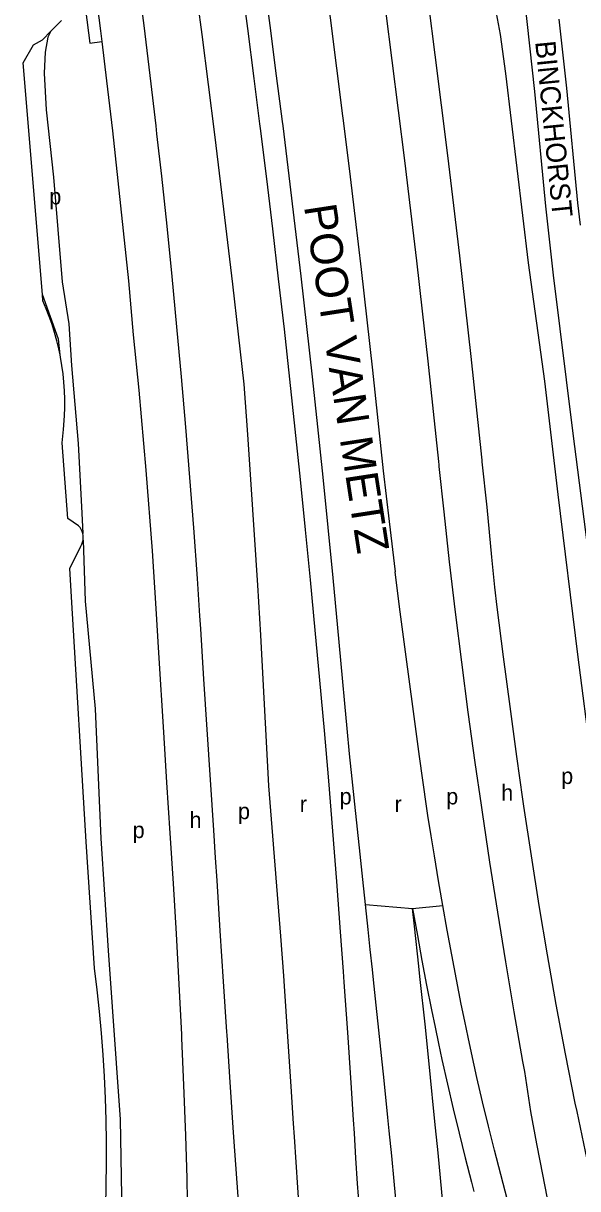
# Model space of a CAD drawing. Extents: x 157646 to 159241, y 379213 to 381217.
# Drawn here: x 157924.4 to 158061.7, y 379962.3 to 380250.8 of the extents above; entities that cross this region are included whole.
import ezdxf

# ---------------------------------------------------------------- set-up
doc = ezdxf.new("R2010")
doc.units = 0
for name, color, linetype in [('BLT_Basislijn', 7, 'Continuous'), ('BLT_Centroide', 7, 'Continuous'), ('BLT_Gemeentegrens', 7, 'Continuous'), ('BLT_Straatnaam', 7, 'Continuous'), ('BLT_Straatnaam_hoofdweg', 7, 'Continuous'), ('BLT_Vlakafsluiter', 7, 'Continuous')]:
    doc.layers.add(name, color=color, linetype=linetype)

msp = doc.modelspace()

# ---------------------------------------------------------------- linework, layer by layer
at = {"layer": 'BLT_Basislijn'}
for points in [[(157939.43, 380280.31), (157940.34, 380273.64), (157941.97, 380261.3), (157943.53, 380248.95), (157943.85, 380246.32)], [(158043.52, 380272.26), (158043.86, 380272.1), (158045.23, 380270.58), (158046.3, 380268.97), (158047.18, 380265.9), (158048.5, 380256.56), (158050.97, 380233.98), (158053.72, 380205.54), (158055.59, 380188.47), (158060.48, 380149.25), (158065.1, 380113.27), (158072.13, 380063.15), (158075.51, 380040.61), (158083.37, 379989.94), (158090.54, 379947.99)], [(158026.51, 380266.17), (158028.27, 380266.84), (158030.04, 380266.89), (158032.44, 380266.09), (158034.37, 380265.02), (158036.46, 380263.3), (158038.06, 380261.59), (158039.72, 380259.45), (158040.69, 380257.15), (158041.27, 380254.63), (158042.46, 380248.09), (158043.78, 380238.44), (158049.4, 380191.53), (158053.5, 380162.19), (158056.77, 380134.16), (158061.6, 380094.53), (158065.06, 380068.3), (158072.73, 380012.87), (158077.32, 379983.19), (158084.04, 379946.64)], [(158012.95, 380262.61), (158014.09, 380254.03), (158015.7, 380241.63), (158017.27, 380229.24)], [(157999.24, 380260.63), (158000.36, 380252.21), (158001.97, 380239.76), (158003.47, 380227.91)], [(157983.01, 380225.94), (157981.59, 380237.15), (157979.98, 380249.54), (157978.9, 380257.67)], [(157988.59, 380226.48), (157987.14, 380237.86), (157985.53, 380250.27), (157984.44, 380258.48)], [(157939.8, 380254.28), (157940.91, 380245.93), (157943.85, 380246.32)], [(157953.78, 380254.03), (157954.25, 380250.28), (157955.76, 380237.87), (157957.21, 380225.45), (157957.43, 380223.47)], [(157967.52, 380256.02), (157968.58, 380248.04), (157970.18, 380235.69), (157971.75, 380223.33), (157973.27, 380210.97), (157974.76, 380198.6), (157976.21, 380186.23), (157977.62, 380173.86), (157978.99, 380161.48), (157979.9, 380149.05), (157980.76, 380136.62), (157981.59, 380124.18), (157982.37, 380111.75), (157983.12, 380099.32), (157983.83, 380086.88), (157984.5, 380074.45), (157985.13, 380062.01), (157986.15, 380049.61), (157987.14, 380037.2), (157988.08, 380024.79), (157988.8, 380014.99), (157988.99, 380012.38), (157989.86, 379999.97), (157990.68, 379987.55), (157991.27, 379978.4), (157991.48, 379975.11), (157991.87, 379968.85), (157992.28, 379962.57), (157992.72, 379956.27)], [(158061.1, 379983.47), (158058.68, 379995.67), (158056.39, 380007.9), (158054.21, 380020.14), (158052.15, 380032.41), (158050.23, 380044.69), (158048.39, 380056.99), (158048.14, 380058.72), (158046.62, 380069.3), (158044.93, 380081.63), (158043.31, 380093.96), (158041.78, 380106.3), (158041.18, 380111.24), (158040.43, 380118.66), (158039.23, 380131.04), (158038.05, 380142.24), (158038.03, 380142.42), (158038.01, 380142.63), (158037.93, 380143.42), (158036.62, 380155.88), (158035.28, 380168.34), (158033.9, 380180.8), (158032.48, 380193.25), (158031.02, 380205.7), (158029.52, 380218.14), (158027.98, 380230.58), (158026.41, 380243.01), (158024.79, 380255.44)], [(158057.05, 380251.88), (158058.92, 380234.8), (158061.68, 380206.36), (158062.28, 380200.88)], [(157931.26, 380248.87), (157930.46, 380247.36), (157929.82, 380243.72), (157929.55, 380238.48), (157930.03, 380229.38), (157931.89, 380212.75), (157934.05, 380186.8), (157935.64, 380176.4), (157936.32, 380166.13), (157937.96, 380146.78), (157938.94, 380129.57), (157939.13, 380124.53)], [(157943.85, 380246.32), (157945.04, 380236.59), (157946.48, 380224.23), (157947.85, 380211.86), (157949.17, 380199.48), (157950.43, 380187.09), (157951.62, 380173.67), (157952.99, 380160.03), (157954.75, 380140.2), (157956.28, 380120.24), (157957.25, 380105.96), (157957.91, 380094.92), (157959.09, 380075.28), (157959.9, 380062.81), (157960.71, 380050.34), (157961.51, 380037.86), (157962.26, 380025.38), (157962.94, 380012.9), (157963.55, 380000.42), (157963.59, 379999.54), (157964.09, 379987.92), (157964.56, 379975.43)], [(158003.47, 380227.91), (158003.55, 380227.31), (158005.09, 380214.85), (158006.59, 380202.38), (158008.05, 380189.91), (158009.47, 380177.43), (158010.85, 380164.96), (158012.2, 380152.47), (158013.5, 380139.98), (158014.97, 380127.51), (158016.49, 380115.05)], [(158017.27, 380229.24), (158017.27, 380229.23), (158018.8, 380216.83), (158020.29, 380204.42), (158021.75, 380192.01), (158023.17, 380179.59), (158024.54, 380167.17), (158025.88, 380154.74), (158027.18, 380142.31), (158027.27, 380141.52), (158027.29, 380141.32), (158027.31, 380141.13), (158028.5, 380129.88), (158029.89, 380117.45), (158031.35, 380105.04), (158032.9, 380092.63), (158034.52, 380080.23), (158036.22, 380067.84), (158037.75, 380057.2), (158038, 380055.47), (158039.85, 380043.1), (158041.79, 380030.75), (158043.79, 380018.41), (158045.88, 380006.08), (158048.04, 379993.77), (158048.49, 379991.31), (158049.99, 379981.41), (158051.5, 379973.34), (158052.31, 379969.13), (158054.7, 379956.85)], [(158007.63, 379957.32), (158007.2, 379963.57), (158006.79, 379969.81), (158006.4, 379976.05), (158006.19, 379979.33), (158005.6, 379988.52), (158004.77, 380000.98), (158003.9, 380013.45), (158003.71, 380016.06), (158002.99, 380025.9), (158002.04, 380038.36), (158001.06, 380050.81), (158000.03, 380063.26), (157998.97, 380075.71), (157997.86, 380088.15), (157996.72, 380100.59), (157995.54, 380113.02), (157994.32, 380125.45), (157993.06, 380137.88), (157991.76, 380150.3), (157990.42, 380162.72), (157989.05, 380175.14), (157987.63, 380187.55), (157986.18, 380199.96), (157984.69, 380212.36), (157983.16, 380224.76), (157983.01, 380225.94)], [(158009.14, 380032.63), (158008.46, 380038.86), (158007.8, 380045.08), (158007.14, 380051.3), (158006.48, 380057.52), (158005.84, 380063.75), (158005.22, 380069.97), (158004.61, 380076.2), (158004.01, 380082.42), (158003.44, 380088.65), (158002.3, 380101.11), (158001.11, 380113.56), (157999.89, 380126.01), (157998.63, 380138.45), (157997.33, 380150.9), (157995.99, 380163.33), (157994.61, 380175.77), (157993.2, 380188.19), (157991.74, 380200.62), (157990.25, 380213.04), (157988.72, 380225.45), (157988.59, 380226.48)], [(157957.43, 380223.47), (157958.59, 380213.02), (157959.91, 380200.59), (157961.17, 380188.15), (157962.37, 380175.71), (157963.51, 380163.26), (157964.58, 380150.8), (157965.59, 380138.34), (157966.54, 380125.88), (157967.43, 380113.4), (157968.05, 380104.09), (157968.25, 380100.93), (157969.06, 380088.46), (157969.87, 380075.98), (157970.68, 380063.51), (157971.49, 380051.03), (157971.93, 380044.23)], [(157933.51, 380168.73), (157933.14, 380172.65), (157929.13, 380183.68)], [(157939.19, 380122.86), (157939.76, 380107.77), (157942.22, 380081.05), (157943.61, 380048.96), (157945.41, 380021.26), (157948.42, 379979.43), (157948.94, 379946.33), (157948.13, 379919.94), (157948.45, 379894.86), (157946.98, 379860.6), (157943.7, 379835.03), (157942.15, 379812.53), (157941.26, 379794.25)], [(158028.29, 380032.4), (158027.47, 380037.13), (158027.23, 380038.53), (158026.21, 380044.66), (158025.4, 380049.68), (158024.59, 380054.71), (158024.27, 380056.96), (158022.52, 380069.3), (158020.83, 380081.64), (158019.18, 380093.98), (158017.59, 380106.34), (158016.49, 380115.05)], [(157971.93, 380044.23), (157972.29, 380038.56), (157973.1, 380026.09), (157973.91, 380013.61), (157974.72, 380001.14), (157974.78, 380000.26), (157975.53, 379988.67), (157976.34, 379976.19), (157977.26, 379963.73), (157978.19, 379951.26), (157979.11, 379938.79), (157979.92, 379926.32), (157980.73, 379913.85)], [(158016.85, 379957.97), (158016.24, 379964.17), (158015.63, 379970.38), (158015.02, 379976.6), (158014.7, 379979.87), (158013.78, 379989.05), (158013.14, 379995.28), (158012.48, 380001.51), (158011.82, 380007.74), (158011.16, 380013.96), (158010.87, 380016.58), (158010.34, 380021.5), (158009.81, 380026.41), (158009.14, 380032.63)], [(158020.8, 380031.65), (158021.99, 380024.95), (158023.11, 380018.8), (158024.28, 380012.66), (158025.5, 380006.52), (158026.37, 380002.24), (158027.21, 379998.25), (158028.07, 379994.27), (158029.43, 379988.17), (158030.85, 379982.07), (158032.31, 379975.99), (158033.83, 379969.92), (158035.4, 379963.86), (158035.99, 379961.61)], [(158028.33, 379958.79), (158027.71, 379964.94), (158027.11, 379971.12), (158026.5, 379977.32), (158026.18, 379980.59), (158025.25, 379989.8), (158023.96, 380002.29), (158022.63, 380014.78), (158022.34, 380017.4), (158021.28, 380027.27), (158020.8, 380031.65)], [(158044.25, 379959.79), (158043.24, 379963.54), (158042.65, 379965.77), (158041.1, 379971.77), (158039.6, 379977.78), (158038.15, 379983.8), (158036.75, 379989.83), (158035.4, 379995.88), (158034.55, 379999.82), (158033.72, 380003.76), (158032.85, 380008), (158031.65, 380014.08), (158030.49, 380020.18), (158029.37, 380026.28), (158028.29, 380032.4)], [(158072.5, 379932.76), (158071.31, 379937.57), (158070.15, 379942.39), (158069.57, 379944.86), (158067.13, 379955.38), (158066.77, 379956.99), (158064.09, 379969.16), (158064.01, 379969.53), (158061.53, 379981.35), (158061.1, 379983.47)], [(157964.56, 379975.43), (157964.9, 379964.81), (157964.94, 379963.61), (157965.27, 379951.11), (157965.38, 379945.95), (157965.53, 379938.61), (157965.72, 379926.12), (157965.82, 379915.79), (157965.83, 379913.62), (157965.87, 379905.85)]]:
    msp.add_lwpolyline(points, dxfattribs=at)
at = {"layer": 'BLT_Gemeentegrens'}
for points in [[(157931.26, 380248.87), (157933.83, 380251.5)], [(157929.13, 380183.68), (157924.41, 380241.04), (157926.94, 380245.51), (157929.2, 380246.77), (157931.26, 380248.87)], [(157933.51, 380168.73), (157933.21, 380170.21), (157932.72, 380172.24), (157932.16, 380174.25), (157931.54, 380176.25), (157930.85, 380178.22), (157930.09, 380180.16), (157929.27, 380182.09), (157929.13, 380183.68)], [(157939.13, 380124.53), (157938.97, 380125.04), (157938.74, 380125.52), (157938.45, 380125.98), (157938.1, 380126.39), (157935.46, 380128.22), (157934.04, 380146.94), (157934.34, 380150.27), (157934.58, 380153.6), (157934.66, 380155.69), (157934.66, 380157.78), (157934.6, 380159.87), (157934.46, 380161.95), (157934.25, 380164.03), (157933.97, 380166.1), (157933.63, 380168.16), (157933.51, 380168.73)], [(157939.19, 380122.86), (157939.2, 380122.91), (157939.25, 380123.45), (157939.23, 380123.99), (157939.13, 380124.52), (157939.13, 380124.53)], [(157944.83, 379957.74), (157944.96, 379963.12), (157945.02, 379968.51), (157945, 379973.89), (157944.9, 379979.28), (157944.73, 379984.66), (157944.48, 379990.04), (157944.15, 379995.41), (157943.74, 380000.79), (157943.26, 380006.15), (157942.7, 380011.5), (157942.07, 380016.85), (157940.01, 380048.18), (157936.41, 380107.39), (157935.89, 380115.87), (157938.64, 380121.4), (157938.9, 380121.87), (157939.08, 380122.38), (157939.19, 380122.86)]]:
    msp.add_lwpolyline(points, dxfattribs=at)
at = {"layer": 'BLT_Vlakafsluiter'}
for p, q in [((158009.14, 380032.63), (158020.8, 380031.65)), ((158020.8, 380031.65), (158028.29, 380032.4))]:
    msp.add_line(p, q, dxfattribs=at)

# ---------------------------------------------------------------- texts
at = {"layer": 'BLT_Centroide'}
for s, p in [('p', (157930.84, 380205.98)), ('p', (158057.6, 380062.48)), ('p', (158002.74, 380057.42)), ('p', (158029.13, 380057.42)), ('h', (158042.74, 380058.32)), ('r', (157992.86, 380055.53)), ('r', (158016.35, 380055.53)), ('h', (157965.56, 380051.56)), ('p', (157977.57, 380053.76)), ('p', (157951.48, 380049.08))]:
    msp.add_text(s, height=4, dxfattribs=at).set_placement(p)
at = {"layer": 'BLT_Straatnaam'}
msp.add_text('BINCKHORST', height=5, rotation=275.685, dxfattribs=at).set_placement((158051.15, 380246.26))
at = {"layer": 'BLT_Straatnaam_hoofdweg'}
msp.add_text('POOT VAN METZ', height=8, rotation=278.7543, dxfattribs=at).set_placement((157993.89, 380205.52))

doc.saveas('drawing.dxf')
